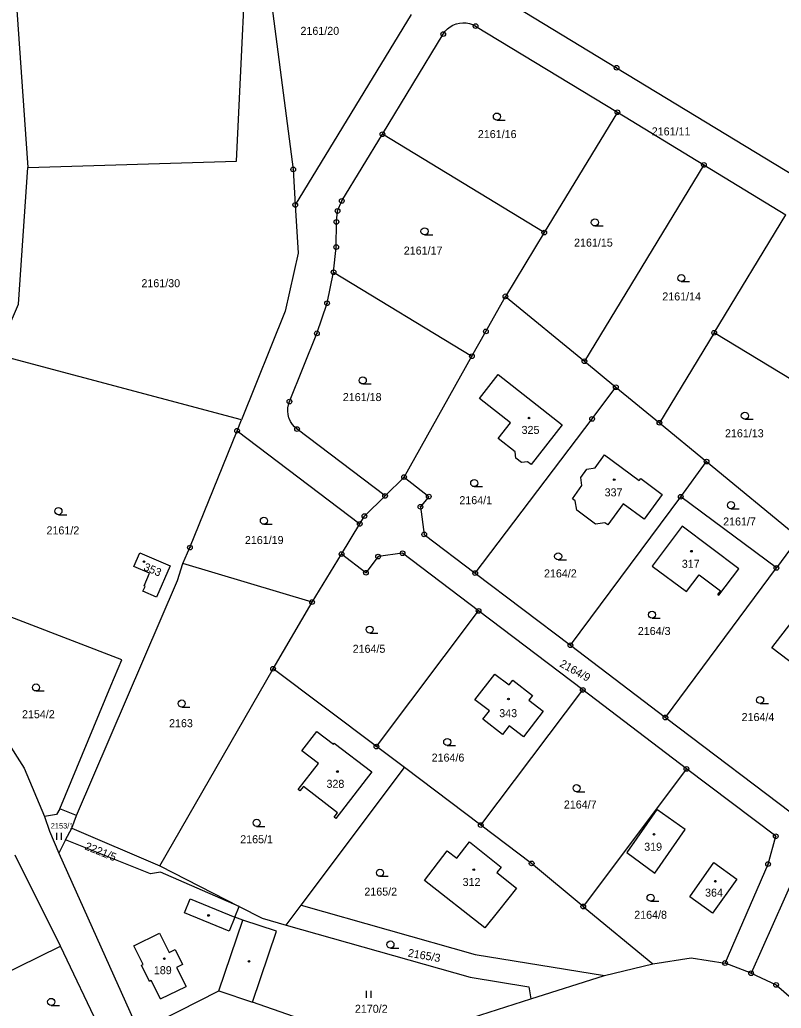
# Model space of a CAD drawing. Extents: x -725728 to -720881, y -1068679 to -1063504.
# Drawn here: x -721645.9 to -721484.1, y -1066663.8 to -1066453.8 of the extents above; entities that cross this region are included whole.
import ezdxf

# ---------------------------------------------------------------- set-up
doc = ezdxf.new("R2010")
doc.units = 0
for name, color, linetype in [('Hranice parcel', 7, 'Continuous'), ('Parcelní čísla', 7, 'Continuous'), ('Vnitřní kresba', 7, 'Continuous'), ('Značky bodu BP', 7, 'Continuous'), ('Značky budov', 7, 'Continuous'), ('Značky kultur', 7, 'Continuous')]:
    doc.layers.add(name, color=color, linetype=linetype)

msp = doc.modelspace()

# ---------------------------------------------------------------- linework, layer by layer
at = {"layer": 'Hranice parcel'}
for p, q in [((-721562.72, -1066452.68), (-721587.32, -1066493.14)), ((-721549.02, -1066455.16), (-721518.9, -1066473.47)), ((-721568.82, -1066478.12), (-721555.89, -1066456.84)), ((-721518.9, -1066473.47), (-721534.43, -1066499.02)), ((-721518.9, -1066473.47), (-721500.53, -1066484.64)), ((-721534.43, -1066499.02), (-721568.82, -1066478.12)), ((-721500.53, -1066484.64), (-721525.89, -1066526.36)), ((-721500.53, -1066484.64), (-721483.09, -1066495.24)), ((-721498.34, -1066520.32), (-721483.09, -1066495.24)), ((-721534.43, -1066499.02), (-721542.67, -1066512.58)), ((-721579.19, -1066507.45), (-721549.81, -1066525.31)), ((-721542.67, -1066512.58), (-721525.89, -1066526.36)), ((-721498.34, -1066520.32), (-721509.96, -1066539.43)), ((-721467.34, -1066539.16), (-721498.34, -1066520.32)), ((-721598.75, -1066538.79), (-721650.78, -1066524.94)), ((-721564.21, -1066550.98), (-721549.81, -1066525.31)), ((-721525.89, -1066526.36), (-721519.23, -1066531.88)), ((-721519.23, -1066531.88), (-721509.96, -1066539.43)), ((-721599.7, -1066541.15), (-721598.75, -1066538.79)), ((-721509.96, -1066539.43), (-721499.96, -1066547.69)), ((-721599.7, -1066541.15), (-721573.64, -1066560.93)), ((-721568.26, -1066554.97), (-721586.95, -1066540.78)), ((-721505.44, -1066555.16), (-721499.96, -1066547.69)), ((-721499.96, -1066547.69), (-721480.36, -1066563.81)), ((-721568.26, -1066554.97), (-721564.21, -1066550.98)), ((-721528.89, -1066586.71), (-721505.44, -1066555.16)), ((-721485.1, -1066570.29), (-721505.44, -1066555.16)), ((-721577.5, -1066567.36), (-721573.64, -1066560.93)), ((-721480.36, -1066563.81), (-721485.1, -1066570.29)), ((-721583.76, -1066577.54), (-721611.18, -1066569.35)), ((-721583.76, -1066577.54), (-721577.5, -1066567.36)), ((-721549.11, -1066571.39), (-721528.89, -1066586.71)), ((-721508.7, -1066602.07), (-721485.1, -1066570.29)), ((-721592.05, -1066591.7), (-721583.76, -1066577.54)), ((-721570.09, -1066608.25), (-721548.38, -1066579.43)), ((-721526.27, -1066596.2), (-721548.38, -1066579.43)), ((-721528.89, -1066586.71), (-721508.7, -1066602.07)), ((-721616.09, -1066633.57), (-721592.05, -1066591.7)), ((-721570.09, -1066608.25), (-721592.05, -1066591.7)), ((-721547.93, -1066624.94), (-721526.27, -1066596.2)), ((-721504.23, -1066612.98), (-721526.27, -1066596.2)), ((-721508.7, -1066602.07), (-721478.72, -1066624.77)), ((-721564.1, -1066612.71), (-721570.09, -1066608.25)), ((-721586.1, -1066641.92), (-721564.1, -1066612.71)), ((-721547.93, -1066624.94), (-721564.1, -1066612.71)), ((-721504.23, -1066612.98), (-721526.14, -1066642.23)), ((-721633.78, -1066622.92), (-721637.34, -1066621.48)), ((-721634.81, -1066625.56), (-721633.78, -1066622.92)), ((-721636.13, -1066628.09), (-721634.81, -1066625.56)), ((-721634.81, -1066625.56), (-721616.09, -1066633.57)), ((-721636.13, -1066628.09), (-721637.59, -1066630.91)), ((-721637.23, -1066650.63), (-721646.83, -1066631.34)), ((-721637.59, -1066630.91), (-721620.54, -1066668.77)), ((-721616.09, -1066633.57), (-721599.22, -1066642.23)), ((-721589.25, -1066646.17), (-721586.1, -1066641.92)), ((-721526.14, -1066642.23), (-721511.34, -1066654.4)), ((-721652.75, -1066658.33), (-721637.23, -1066650.63)), ((-721627.54, -1066670.91), (-721637.23, -1066650.63)), ((-721521.67, -1066656.92), (-721511.34, -1066654.4)), ((-721490.49, -1066656.42), (-721496.01, -1066654.24)), ((-721537.28, -1066661.87), (-721521.67, -1066656.92)), ((-721569.19, -1066671.99), (-721596.44, -1066662.59)), ((-721569.19, -1066671.99), (-721537.28, -1066661.87))]:
    msp.add_line(p, q, dxfattribs=at)
for points in [[(-721643.54, -1066400.19), (-721646.96, -1066444.65), (-721644.13, -1066485.2)], [(-721592.64, -1066419.28), (-721519.06, -1066464.02), (-721445.47, -1066508.75)], [(-721644.13, -1066485.2), (-721599.78, -1066483.83), (-721597.03, -1066426.14)], [(-721593.65, -1066428.03), (-721593.55, -1066440.99), (-721587.77, -1066485.61), (-721587.32, -1066493.14)], [(-721555.89, -1066456.84), (-721555.48, -1066456.26), (-721554.99, -1066455.75), (-721554.44, -1066455.31), (-721553.83, -1066454.95), (-721553.17, -1066454.69), (-721553.11, -1066454.67), (-721552.43, -1066454.5), (-721551.72, -1066454.44), (-721551.01, -1066454.47), (-721550.32, -1066454.61), (-721549.65, -1066454.84), (-721549.02, -1066455.16)], [(-721579.19, -1066507.45), (-721578.64, -1066502.11), (-721578.6, -1066496.75), (-721578.35, -1066494.44), (-721577.44, -1066492.29), (-721568.82, -1066478.12)], [(-721650.78, -1066524.94), (-721646.1, -1066514.21), (-721644.13, -1066485.2)], [(-721587.32, -1066493.14), (-721586.7, -1066503.43), (-721589.44, -1066515.7), (-721598.75, -1066538.79)], [(-721588.56, -1066534.93), (-721582.73, -1066520.44), (-721580.58, -1066514.05), (-721579.19, -1066507.45)], [(-721549.81, -1066525.31), (-721546.84, -1066520.02), (-721542.67, -1066512.58)], [(-721544.24, -1066542.81), (-721541.6, -1066539.43), (-721548.21, -1066534.26), (-721544.26, -1066529.22), (-721530.65, -1066539.86), (-721537.25, -1066548.28), (-721537.97, -1066547.71), (-721539.3, -1066547.85), (-721540.44, -1066546.97), (-721540.61, -1066545.64), (-721544.24, -1066542.81)], [(-721549.11, -1066571.39), (-721524.26, -1066538.62), (-721519.23, -1066531.88)], [(-721586.95, -1066540.78), (-721587.48, -1066540.32), (-721587.94, -1066539.78), (-721588.32, -1066539.19), (-721588.61, -1066538.55), (-721588.67, -1066538.38), (-721588.85, -1066537.7), (-721588.93, -1066537), (-721588.9, -1066536.3), (-721588.78, -1066535.6), (-721588.56, -1066534.93)], [(-721611.18, -1066569.35), (-721609.7, -1066565.97), (-721599.7, -1066541.15)], [(-721527.9, -1066556.04), (-721528.43, -1066555.58), (-721526.45, -1066552.8), (-721526.67, -1066551.1), (-721525.37, -1066549.3), (-721523.63, -1066549.03), (-721521.63, -1066546.29), (-721514.26, -1066551.71), (-721513.93, -1066551.32), (-721509.38, -1066554.66), (-721513.24, -1066559.91), (-721517.68, -1066556.7), (-721520.93, -1066561.11), (-721521.57, -1066560.68), (-721523.55, -1066560.96), (-721527.5, -1066558.04), (-721527.9, -1066556.04)], [(-721564.21, -1066550.98), (-721558.97, -1066555.11), (-721560.74, -1066557.29), (-721559.94, -1066563.17), (-721549.11, -1066571.39)], [(-721573.64, -1066560.93), (-721572.63, -1066559.26), (-721568.26, -1066554.97)], [(-721497.61, -1066575.93), (-721497.35, -1066576.1), (-721493.12, -1066570.45), (-721505.17, -1066561.44), (-721511.48, -1066569.89), (-721504.22, -1066575.29), (-721501.54, -1066571.73), (-721497.01, -1066575.13), (-721497.61, -1066575.93)], [(-721619.23, -1066574.21), (-721619.46, -1066574.11), (-721618.29, -1066571.39), (-721621.59, -1066569.97), (-721620.35, -1066567.11), (-721613.93, -1066569.82), (-721616.81, -1066576.49), (-721619.69, -1066575.26), (-721619.23, -1066574.21)], [(-721548.38, -1066579.43), (-721564.54, -1066567.17), (-721569.72, -1066567.89), (-721572.32, -1066571.31), (-721577.5, -1066567.36)], [(-721633.78, -1066622.92), (-721612.38, -1066572.94), (-721611.18, -1066569.35)], [(-721637.34, -1066621.48), (-721626.52, -1066595.36), (-721624.19, -1066589.83), (-721667.07, -1066573.34)], [(-721478.7, -1066592.87), (-721486.07, -1066587.25), (-721480.57, -1066580.11)], [(-721549.16, -1066598.29), (-721544.93, -1066592.86), (-721541.91, -1066595.12), (-721541.11, -1066594.14), (-721536.92, -1066597.38), (-721537.71, -1066598.41), (-721534.7, -1066600.72), (-721538.88, -1066606.17), (-721541.9, -1066603.85), (-721543.29, -1066605.68), (-721547.51, -1066602.45), (-721546.09, -1066600.63), (-721549.16, -1066598.29)], [(-721658.3, -1066602.64), (-721648.73, -1066606.85), (-721644.95, -1066612.83), (-721640.59, -1066623.09)], [(-721586.69, -1066617.36), (-721582.42, -1066611.84), (-721585.96, -1066609.17), (-721582.75, -1066605.05), (-721579.24, -1066607.73), (-721579.09, -1066607.54), (-721571.08, -1066613.6), (-721578.71, -1066623.54), (-721579.07, -1066623.26), (-721578.34, -1066622.32), (-721585.6, -1066616.7), (-721586.33, -1066617.64), (-721586.69, -1066617.36)], [(-721496.01, -1066654.24), (-721486.9, -1066633.21), (-721485.27, -1066627.3), (-721504.23, -1066612.98)], [(-721637.34, -1066621.48), (-721638.02, -1066622.65), (-721640.59, -1066623.09)], [(-721504.47, -1066625.9), (-721510.51, -1066621.65), (-721516.91, -1066630.75), (-721510.91, -1066635.12), (-721504.47, -1066625.9)], [(-721640.59, -1066623.09), (-721639.54, -1066626.25), (-721637.59, -1066630.91)], [(-721526.14, -1066642.23), (-721537.11, -1066633.09), (-721547.93, -1066624.94)], [(-721478.72, -1066624.77), (-721481.16, -1066635.44), (-721490.49, -1066656.42)], [(-721599.22, -1066642.23), (-721615.97, -1066634.96), (-721618.07, -1066635.28), (-721636.13, -1066628.09)], [(-721544.5, -1066635.02), (-721540.3, -1066638.35), (-721544.14, -1066643.16), (-721547.05, -1066646.79), (-721559.87, -1066636.72), (-721555.03, -1066630.37), (-721553.03, -1066631.96), (-721550.29, -1066628.51), (-721543.57, -1066633.85), (-721544.5, -1066635.02)], [(-721498.4, -1066632.88), (-721493.52, -1066636.41), (-721498.66, -1066643.62), (-721503.52, -1066640.15), (-721498.4, -1066632.88)], [(-721596.44, -1066662.59), (-721591.33, -1066647.44), (-721598.48, -1066645.15), (-721600.17, -1066644.53), (-721599.22, -1066642.23)], [(-721599.22, -1066642.23), (-721594.38, -1066644.72), (-721589.25, -1066646.17)], [(-721586.1, -1066641.92), (-721549.11, -1066652.4), (-721521.67, -1066656.92)], [(-721589.25, -1066646.17), (-721550.17, -1066657.23), (-721537.69, -1066659.29), (-721537.28, -1066661.87)], [(-721511.34, -1066654.4), (-721503.23, -1066653.17), (-721496.01, -1066654.24)], [(-721490.49, -1066656.42), (-721485.18, -1066658.89), (-721471.92, -1066670.45)], [(-721620.54, -1066668.77), (-721603.6, -1066660.12), (-721596.44, -1066662.59)]]:
    msp.add_lwpolyline(points, dxfattribs=at)
at = {"layer": 'Vnitřní kresba'}
for p, q in [((-721610.88, -1066643.59), (-721609.66, -1066640.63)), ((-721609.66, -1066640.63), (-721600.17, -1066644.53)), ((-721601.37, -1066647.44), (-721610.88, -1066643.59)), ((-721600.17, -1066644.53), (-721601.37, -1066647.44)), ((-721603.6, -1066660.12), (-721598.48, -1066645.15)), ((-721621.59, -1066650.58), (-721616.19, -1066647.9)), ((-721616.19, -1066647.9), (-721614.14, -1066652.02)), ((-721619.62, -1066654.53), (-721621.59, -1066650.58)), ((-721614.14, -1066652.02), (-721612.82, -1066651.37)), ((-721612.82, -1066651.37), (-721611.25, -1066654.52)), ((-721620.01, -1066654.73), (-721619.62, -1066654.53)), ((-721618.31, -1066658.15), (-721620.01, -1066654.73)), ((-721611.25, -1066654.52), (-721612.56, -1066655.18)), ((-721612.56, -1066655.18), (-721610.53, -1066659.26)), ((-721617.91, -1066657.96), (-721618.31, -1066658.15)), ((-721615.97, -1066661.86), (-721617.91, -1066657.96)), ((-721615.97, -1066661.86), (-721610.53, -1066659.26))]:
    msp.add_line(p, q, dxfattribs=at)
at = {"layer": 'Značky bodu BP'}
for centre, radius in [((-721549.02, -1066455.16), 0.5), ((-721549.02, -1066455.16), 0.0303), ((-721555.89, -1066456.84), 0.5), ((-721555.89, -1066456.84), 0.0303), ((-721519.06, -1066464.02), 0.5), ((-721519.06, -1066464.02), 0.0303), ((-721518.9, -1066473.47), 0.5), ((-721518.9, -1066473.47), 0.0303), ((-721568.82, -1066478.12), 0.5), ((-721568.82, -1066478.12), 0.0303), ((-721587.77, -1066485.61), 0.5), ((-721500.53, -1066484.64), 0.5), ((-721500.53, -1066484.64), 0.0303), ((-721587.77, -1066485.61), 0.0303), ((-721587.32, -1066493.14), 0.5), ((-721587.32, -1066493.14), 0.0303), ((-721577.44, -1066492.29), 0.5), ((-721577.44, -1066492.29), 0.0303), ((-721578.35, -1066494.44), 0.5), ((-721578.35, -1066494.44), 0.0303), ((-721578.6, -1066496.75), 0.5), ((-721578.6, -1066496.75), 0.0303), ((-721534.43, -1066499.02), 0.5), ((-721534.43, -1066499.02), 0.0303), ((-721578.64, -1066502.11), 0.5), ((-721578.64, -1066502.11), 0.0303), ((-721579.19, -1066507.45), 0.5), ((-721579.19, -1066507.45), 0.0303), ((-721542.67, -1066512.58), 0.5), ((-721542.67, -1066512.58), 0.0303), ((-721580.58, -1066514.05), 0.5), ((-721580.58, -1066514.05), 0.0303), ((-721582.73, -1066520.44), 0.5), ((-721582.73, -1066520.44), 0.0303), ((-721546.84, -1066520.02), 0.5), ((-721546.84, -1066520.02), 0.0303), ((-721498.34, -1066520.32), 0.5), ((-721498.34, -1066520.32), 0.0303), ((-721549.81, -1066525.31), 0.5), ((-721549.81, -1066525.31), 0.0303), ((-721525.89, -1066526.36), 0.5), ((-721525.89, -1066526.36), 0.0303), ((-721519.23, -1066531.88), 0.5), ((-721519.23, -1066531.88), 0.0303), ((-721588.56, -1066534.93), 0.5), ((-721588.56, -1066534.93), 0.0303), ((-721524.26, -1066538.62), 0.5), ((-721524.26, -1066538.62), 0.0303), ((-721509.96, -1066539.43), 0.5), ((-721509.96, -1066539.43), 0.0303), ((-721599.7, -1066541.15), 0.5), ((-721599.7, -1066541.15), 0.0303), ((-721586.95, -1066540.78), 0.5), ((-721586.95, -1066540.78), 0.0303), ((-721499.96, -1066547.69), 0.5), ((-721499.96, -1066547.69), 0.0303), ((-721564.21, -1066550.98), 0.5), ((-721564.21, -1066550.98), 0.0303), ((-721568.26, -1066554.97), 0.5), ((-721558.97, -1066555.11), 0.5), ((-721505.44, -1066555.16), 0.5), ((-721568.26, -1066554.97), 0.0303), ((-721560.74, -1066557.29), 0.5), ((-721558.97, -1066555.11), 0.0303), ((-721505.44, -1066555.16), 0.0303), ((-721572.63, -1066559.26), 0.5), ((-721560.74, -1066557.29), 0.0303), ((-721573.64, -1066560.93), 0.5), ((-721573.64, -1066560.93), 0.0303), ((-721572.63, -1066559.26), 0.0303), ((-721559.94, -1066563.17), 0.5), ((-721559.94, -1066563.17), 0.0303), ((-721609.7, -1066565.97), 0.5), ((-721609.7, -1066565.97), 0.0303), ((-721577.5, -1066567.36), 0.5), ((-721564.54, -1066567.17), 0.5), ((-721564.54, -1066567.17), 0.0303), ((-721577.5, -1066567.36), 0.0303), ((-721569.72, -1066567.89), 0.5), ((-721569.72, -1066567.89), 0.0303), ((-721572.32, -1066571.31), 0.5), ((-721572.32, -1066571.31), 0.0303), ((-721549.11, -1066571.39), 0.5), ((-721549.11, -1066571.39), 0.0303), ((-721485.1, -1066570.29), 0.5), ((-721485.1, -1066570.29), 0.0303), ((-721583.76, -1066577.54), 0.5), ((-721583.76, -1066577.54), 0.0303), ((-721548.38, -1066579.43), 0.5), ((-721548.38, -1066579.43), 0.0303), ((-721528.89, -1066586.71), 0.5), ((-721528.89, -1066586.71), 0.0303), ((-721592.05, -1066591.7), 0.5), ((-721592.05, -1066591.7), 0.0303), ((-721526.27, -1066596.2), 0.5), ((-721526.27, -1066596.2), 0.0303), ((-721508.7, -1066602.07), 0.5), ((-721508.7, -1066602.07), 0.0303), ((-721570.09, -1066608.25), 0.5), ((-721570.09, -1066608.25), 0.0303), ((-721504.23, -1066612.98), 0.5), ((-721504.23, -1066612.98), 0.0303), ((-721547.93, -1066624.94), 0.5), ((-721547.93, -1066624.94), 0.0303), ((-721485.27, -1066627.3), 0.5), ((-721485.27, -1066627.3), 0.0303), ((-721537.11, -1066633.09), 0.5), ((-721537.11, -1066633.09), 0.0303), ((-721486.9, -1066633.21), 0.5), ((-721486.9, -1066633.21), 0.0303), ((-721526.14, -1066642.23), 0.5), ((-721526.14, -1066642.23), 0.0303), ((-721496.01, -1066654.24), 0.5), ((-721496.01, -1066654.24), 0.0303), ((-721490.49, -1066656.42), 0.5), ((-721490.49, -1066656.42), 0.0303), ((-721485.18, -1066658.89), 0.5), ((-721485.18, -1066658.89), 0.0303)]:
    msp.add_circle(centre, radius, dxfattribs=at)
at = {"layer": 'Značky budov'}
for centre in [(-721537.67, -1066538.43), (-721519.57, -1066551.55), (-721503.17, -1066566.73), (-721619.48, -1066568.95), (-721542.04, -1066598.14), (-721578.37, -1066613.56), (-721511.11, -1066626.89), (-721549.4, -1066634.41), (-721498.09, -1066636.86), (-721605.75, -1066644.13), (-721615.14, -1066653.32), (-721597.17, -1066653.89)]:
    msp.add_circle(centre, 0.175, dxfattribs=at)
at = {"layer": 'Značky kultur'}
for p, q in [((-721544.5, -1066475.13), (-721542.75, -1066475.13)), ((-721523.69, -1066497.63), (-721521.94, -1066497.63)), ((-721559.87, -1066499.51), (-721558.12, -1066499.51)), ((-721505.32, -1066509.44), (-721503.57, -1066509.44)), ((-721572.99, -1066531.2), (-721571.24, -1066531.2)), ((-721491.82, -1066538.7), (-721490.07, -1066538.7)), ((-721549.31, -1066553.01), (-721547.56, -1066553.01)), ((-721494.78, -1066557.7), (-721493.03, -1066557.7)), ((-721637.64, -1066558.97), (-721635.89, -1066558.97)), ((-721593.99, -1066561.02), (-721592.24, -1066561.02)), ((-721531.48, -1066568.58), (-721529.73, -1066568.58)), ((-721511.54, -1066580.97), (-721509.79, -1066580.97)), ((-721571.52, -1066584.14), (-721569.77, -1066584.14)), ((-721642.4, -1066596.43), (-721640.65, -1066596.43)), ((-721611.45, -1066599.85), (-721609.7, -1066599.85)), ((-721488.58, -1066599.11), (-721486.83, -1066599.11)), ((-721555.05, -1066608.02), (-721553.3, -1066608.02)), ((-721527.56, -1066617.84), (-721525.81, -1066617.84)), ((-721595.53, -1066625.2), (-721593.78, -1066625.2)), ((-721637.96, -1066628.09), (-721637.96, -1066626.59)), ((-721636.96, -1066628.09), (-721636.96, -1066626.59)), ((-721569.33, -1066635.82), (-721567.58, -1066635.82)), ((-721511.85, -1066641.12), (-721510.1, -1066641.12)), ((-721567.11, -1066651.06), (-721565.36, -1066651.06)), ((-721572.19, -1066661.66), (-721572.19, -1066660.16)), ((-721571.19, -1066661.66), (-721571.19, -1066660.16)), ((-721639.18, -1066663.25), (-721637.43, -1066663.25))]:
    msp.add_line(p, q, dxfattribs=at)
for centre in [(-721544.5, -1066474.38), (-721523.69, -1066496.88), (-721559.87, -1066498.76), (-721505.32, -1066508.69), (-721572.99, -1066530.45), (-721491.82, -1066537.95), (-721549.31, -1066552.26), (-721494.78, -1066556.95), (-721637.64, -1066558.22), (-721593.99, -1066560.27), (-721531.48, -1066567.83), (-721511.54, -1066580.22), (-721571.52, -1066583.39), (-721642.4, -1066595.68), (-721611.45, -1066599.1), (-721488.58, -1066598.36), (-721555.05, -1066607.27), (-721527.56, -1066617.09), (-721595.53, -1066624.45), (-721569.33, -1066635.07), (-721511.85, -1066640.37), (-721567.11, -1066650.31), (-721639.18, -1066662.5)]:
    msp.add_circle(centre, 0.75, dxfattribs=at)

# ---------------------------------------------------------------- texts
at = {"layer": 'Parcelní čísla'}
for s, height, p in [('2161/20', 1.7, (-721586.22, -1066457.01)), ('2161/11', 1.7, (-721511.6, -1066478.38)), ('2161/16', 1.7, (-721548.54, -1066478.95)), ('2161/17', 1.7, (-721564.28, -1066503.7)), ('2161/15', 1.7, (-721528.1, -1066502.01)), ('2161/30', 1.7, (-721620.01, -1066510.64)), ('2161/14', 1.7, (-721509.36, -1066513.45)), ('2161/18', 1.7, (-721577.22, -1066534.83)), ('325', 1.7, (-721539.25, -1066541.81)), ('2161/13', 1.7, (-721496.04, -1066542.52)), ('337', 1.7, (-721521.61, -1066555.08)), ('2164/1', 1.7, (-721552.47, -1066556.74)), ('2161/7', 1.7, (-721496.43, -1066561.27)), ('2161/2', 1.7, (-721640.17, -1066563.16)), ('2161/19', 1.7, (-721598.03, -1066565.21)), ('317', 1.7, (-721505.22, -1066570.26)), ('2164/2', 1.7, (-721534.49, -1066572.3)), ('2164/3', 1.7, (-721514.56, -1066584.54)), ('2164/5', 1.7, (-721575.14, -1066588.32)), ('2154/2', 1.7, (-721645.38, -1066602.22)), ('343', 1.7, (-721544, -1066602)), ('2163', 1.7, (-721614.14, -1066604.13)), ('2164/4', 1.7, (-721492.51, -1066602.83)), ('2164/6', 1.7, (-721558.36, -1066611.44)), ('328', 1.7, (-721580.7, -1066617.01)), ('2164/7', 1.7, (-721530.27, -1066621.41)), ('2153/1', 1.14, (-721639.27, -1066625.65)), ('2165/1', 1.7, (-721599.02, -1066628.79)), ('319', 1.7, (-721513.2, -1066630.38)), ('312', 1.7, (-721551.78, -1066637.87)), ('2165/2', 1.7, (-721572.65, -1066639.92)), ('364', 1.7, (-721500.27, -1066640.13)), ('2164/8', 1.7, (-721515.32, -1066644.84)), ('189', 1.7, (-721617.37, -1066656.61)), ('2170/2', 1.7, (-721574.66, -1066664.81))]:
    msp.add_text(s, height=height, dxfattribs=at).set_placement(p)
for s, rotation, p in [('353', 337, (-721619.71, -1066570.69)), ('2164/9', 331, (-721531.32, -1066591.14)), ('2221/5', 338, (-721632.19, -1066630.05)), ('2165/3', 350, (-721563.5, -1066652.86))]:
    msp.add_text(s, height=1.7, rotation=rotation, dxfattribs=at).set_placement(p)

doc.saveas('drawing.dxf')
